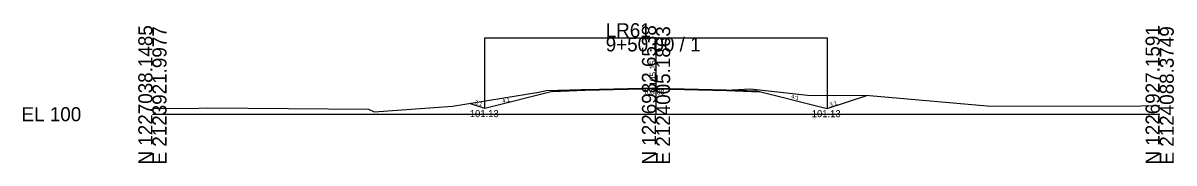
# Model space of a CAD drawing. Extents: x 2121193 to 2127979, y 1225108 to 1234639.
# Drawn here: x 2126750.9 to 2126979.4, y 1234607.5 to 1234635.3 of the extents above; entities that cross this region are included whole.
import ezdxf

# ---------------------------------------------------------------- set-up
doc = ezdxf.new("R2010")
doc.units = 0
for name, color, linetype in [('XS_CELL', 7, 'Continuous'), ('XS_M_DITCH', 7, 'Continuous'), ('XS_P_FINISHED_GRADE', 7, 'Continuous'), ('XS_P_FINISHED_GRADE_ELEV_TX', 7, 'Continuous'), ('XS_P_SUBGRADE_GRANULAR', 7, 'Continuous'), ('XS_P_SUBGRADE_PAVEMENT', 7, 'Continuous'), ('XS_P_TX_DCH', 7, 'Continuous'), ('XS_P_TX_FS_BS', 7, 'Continuous'), ('XS_X_GROUND', 7, 'Continuous'), ('XS_X_GROUND_TX', 7, 'Continuous')]:
    doc.layers.add(name, color=color, linetype=linetype)

msp = doc.modelspace()

# ---------------------------------------------------------------- linework, layer by layer
at = {"layer": 'XS_CELL'}
for p, q in [((2126876.61, 1234617.21), (2126876.61, 1234632.49)), ((2126776.61, 1234617.21), (2126876.61, 1234617.21)), ((2126876.61, 1234617.21), (2126976.61, 1234617.21))]:
    msp.add_line(p, q, dxfattribs=at)
at = {"layer": 'XS_M_DITCH'}
for p, q in [((2126842.61, 1234618.34), (2126842.61, 1234632.39)), ((2126842.61, 1234632.39), (2126910.61, 1234632.39)), ((2126910.61, 1234632.39), (2126910.61, 1234618.34))]:
    msp.add_line(p, q, dxfattribs=at)
at = {"layer": 'XS_P_FINISHED_GRADE'}
for p, q in [((2126876.61, 1234622.36), (2126862.61, 1234622.08)), ((2126876.61, 1234622.36), (2126890.61, 1234622.08)), ((2126856.61, 1234621.84), (2126842.61, 1234618.34)), ((2126862.61, 1234622.08), (2126856.61, 1234621.84)), ((2126890.61, 1234622.08), (2126896.61, 1234621.84)), ((2126896.61, 1234621.84), (2126910.61, 1234618.34)), ((2126910.61, 1234618.34), (2126918.46, 1234620.96)), ((2126842.61, 1234618.34), (2126839.57, 1234619.35))]:
    msp.add_line(p, q, dxfattribs=at)
at = {"layer": 'XS_P_SUBGRADE_GRANULAR'}
for p, q in [((2126862.54, 1234621.95), (2126856.02, 1234621.69)), ((2126890.68, 1234621.95), (2126897.2, 1234621.69))]:
    msp.add_line(p, q, dxfattribs=at)
at = {"layer": 'XS_P_SUBGRADE_PAVEMENT'}
for p, q in [((2126876.61, 1234622.23), (2126862.54, 1234621.95)), ((2126876.61, 1234622.23), (2126890.68, 1234621.95)), ((2126862.61, 1234622.08), (2126862.54, 1234621.95)), ((2126890.61, 1234622.08), (2126890.68, 1234621.95))]:
    msp.add_line(p, q, dxfattribs=at)
at = {"layer": 'XS_X_GROUND'}
for p, q in [((2126866.95, 1234622.17), (2126876.07, 1234622.3)), ((2126876.07, 1234622.3), (2126876.61, 1234622.29)), ((2126876.61, 1234622.29), (2126881.92, 1234622.17)), ((2126890.52, 1234621.99), (2126895.39, 1234622.28)), ((2126895.39, 1234622.28), (2126906.65, 1234621.01)), ((2126836.18, 1234618.8), (2126853.32, 1234621.61)), ((2126853.32, 1234621.61), (2126854.79, 1234621.91)), ((2126854.79, 1234621.91), (2126861.78, 1234622.11)), ((2126861.78, 1234622.11), (2126866.95, 1234622.17)), ((2126881.92, 1234622.17), (2126890.52, 1234621.99)), ((2126906.65, 1234621.01), (2126918.96, 1234620.95)), ((2126918.96, 1234620.95), (2126942.34, 1234618.89)), ((2126776.61, 1234618.42), (2126783.98, 1234618.36)), ((2126783.98, 1234618.36), (2126787.58, 1234618.49)), ((2126787.58, 1234618.49), (2126819.52, 1234618.23)), ((2126819.52, 1234618.23), (2126820.61, 1234617.71)), ((2126820.61, 1234617.71), (2126836.18, 1234618.8)), ((2126942.34, 1234618.89), (2126969.18, 1234618.81)), ((2126969.18, 1234618.81), (2126976.61, 1234618.97))]:
    msp.add_line(p, q, dxfattribs=at)

# ---------------------------------------------------------------- texts
at = {"layer": 'XS_CELL'}
for s, p in [('N 1227038.1485', (2126776.61, 1234607.21)), ('E 2123921.9977', (2126779.41, 1234607.21)), ('N 1226982.6538', (2126876.61, 1234607.21)), ('E 2124005.1863', (2126879.41, 1234607.21)), ('N 1226927.1591', (2126976.61, 1234607.21)), ('E 2124088.3749', (2126979.41, 1234607.21))]:
    msp.add_text(s, height=2.8, rotation=90, dxfattribs=at).set_placement(p)
for s, p in [('LR61', (2126866.61, 1234632.49)), ('9+50.00 / 1', (2126866.61, 1234629.69)), ('EL 100', (2126750.61, 1234615.81))]:
    msp.add_text(s, height=2.8, dxfattribs=at).set_placement(p)
at = {"layer": 'XS_P_FINISHED_GRADE_ELEV_TX'}
msp.add_text(' 105.15', height=1.25, rotation=90, dxfattribs=at).set_placement((2126876.61, 1234622.36))
at = {"layer": 'XS_P_TX_DCH'}
for p in [(2126839.63, 1234616.63), (2126907.53, 1234616.62)]:
    msp.add_text('101.13', height=1.4, dxfattribs=at).set_placement(p)
at = {"layer": 'XS_P_TX_FS_BS'}
for s, rotation, p in [('3:1', 341.5651, (2126840.53, 1234619.26)), ('4:1', 14.0362, (2126846.17, 1234619.4)), ('4:1', 345.9638, (2126903.38, 1234620.4)), ('3:1', 18.4349, (2126911.21, 1234618.68))]:
    msp.add_text(s, height=0.8, rotation=rotation, dxfattribs=at).set_placement(p)
at = {"layer": 'XS_X_GROUND_TX'}
msp.add_text('105.08', height=1, dxfattribs=at).set_placement((2126874.05, 1234621.13))

doc.saveas('drawing.dxf')
